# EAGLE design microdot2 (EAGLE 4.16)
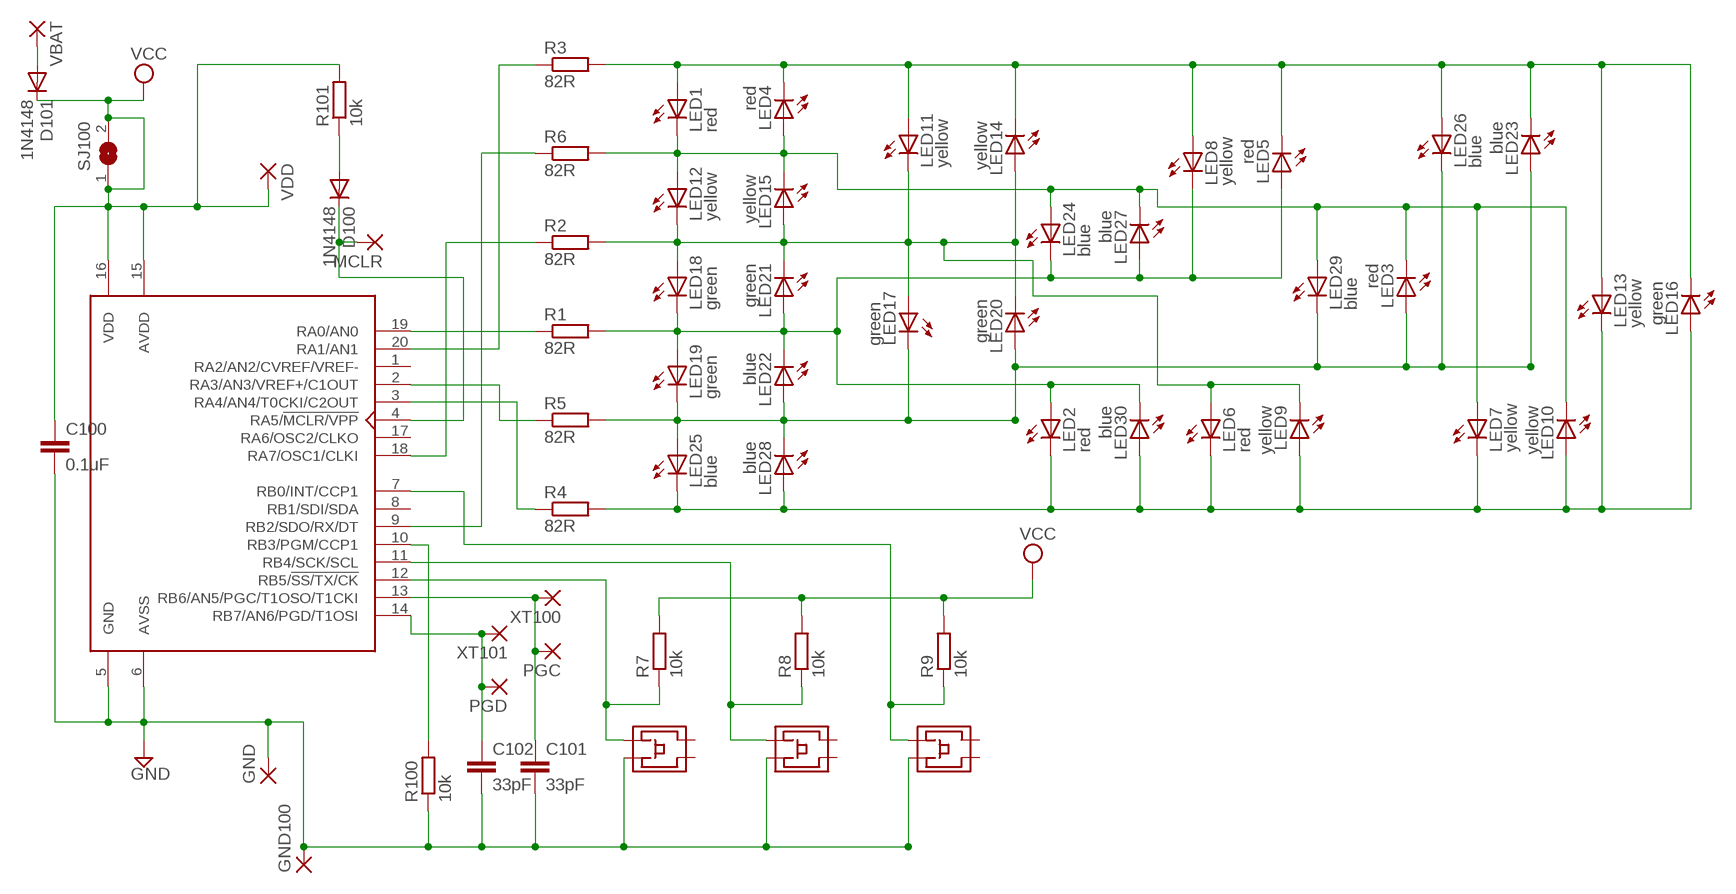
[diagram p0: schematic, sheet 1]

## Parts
C100  0.1uF  C-EUC0805K  [C0805K]
C101  33pF  C-EUC0805K  [C0805K]
C102  33pF  C-EUC0805K  [C0805K]
D100  1N4148  DIODE-MINIMELF  [MINIMELF]
D101  1N4148  DIODE-MINIMELF  [MINIMELF]
GND  SMD5  [SMD5]
GND100  SMD2  [SMD2]
LED1  red  LEDCHIPLED_1206  [CHIPLED_1206]
LED2  red  LEDCHIPLED_1206  [CHIPLED_1206]
LED3  red  LEDCHIPLED_1206  [CHIPLED_1206]
LED4  red  LEDCHIPLED_1206  [CHIPLED_1206]
LED5  red  LEDCHIPLED_1206  [CHIPLED_1206]
LED6  red  LEDCHIPLED_1206  [CHIPLED_1206]
LED7  yellow  LEDCHIPLED_1206  [CHIPLED_1206]
LED8  yellow  LEDCHIPLED_1206  [CHIPLED_1206]
LED9  yellow  LEDCHIPLED_1206  [CHIPLED_1206]
LED10  yellow  LEDCHIPLED_1206  [CHIPLED_1206]
LED11  yellow  LEDCHIPLED_1206  [CHIPLED_1206]
LED12  yellow  LEDCHIPLED_1206  [CHIPLED_1206]
LED13  yellow  LEDCHIPLED_1206  [CHIPLED_1206]
LED14  yellow  LEDCHIPLED_1206  [CHIPLED_1206]
LED15  yellow  LEDCHIPLED_1206  [CHIPLED_1206]
LED16  green  LEDCHIPLED_1206  [CHIPLED_1206]
LED17  green  LEDCHIPLED_1206  [CHIPLED_1206]
LED18  green  LEDCHIPLED_1206  [CHIPLED_1206]
LED19  green  LEDCHIPLED_1206  [CHIPLED_1206]
LED20  green  LEDCHIPLED_1206  [CHIPLED_1206]
LED21  green  LEDCHIPLED_1206  [CHIPLED_1206]
LED22  blue  LEDCHIPLED_1206  [CHIPLED_1206]
LED23  blue  LEDCHIPLED_1206  [CHIPLED_1206]
LED24  blue  LEDCHIPLED_1206  [CHIPLED_1206]
LED25  blue  LEDCHIPLED_1206  [CHIPLED_1206]
LED26  blue  LEDCHIPLED_1206  [CHIPLED_1206]
LED27  blue  LEDCHIPLED_1206  [CHIPLED_1206]
LED28  blue  LEDCHIPLED_1206  [CHIPLED_1206]
LED29  blue  LEDCHIPLED_1206  [CHIPLED_1206]
LED30  blue  LEDCHIPLED_1206  [CHIPLED_1206]
MCLR  SMD2  [SMD2]
PGC  SMD2  [SMD2]
PGD  SMD2  [SMD2]
R1  82R  R-EU_M0805  [M0805]
R2  82R  R-EU_M0805  [M0805]
R3  82R  R-EU_M0805  [M0805]
R4  82R  R-EU_M0805  [M0805]
R5  82R  R-EU_M0805  [M0805]
R6  82R  R-EU_M0805  [M0805]
R7  10k  R-EU_M0805  [M0805]
R8  10k  R-EU_M0805  [M0805]
R9  10k  R-EU_M0805  [M0805]
R100  10k  R-EU_M0805  [M0805]
R101  10k  R-EU_M0805  [M0805]
SJ100  SJ  [SJ]
U100  16F88SOIP20  [SSOP20]
U$1  SMDMICROSWITCH  [SMDMICROSWITCH]
U$2  SMDMICROSWITCH  [SMDMICROSWITCH]
U$3  SMDMICROSWITCH  [SMDMICROSWITCH]
VBAT  SMD5  [SMD5]
VDD  SMD2  [SMD2]
XT100  SMD2  [SMD2]
XT101  SMD2  [SMD2]

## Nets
GND: C100.2 C101.2 C102.2 GND100.1(P) GND.1(P) R100.1 U100.5(GND) U100.6(AVSS) U$1.L1 U$2.L1 U$3.L1
N$1: R1.1 U100.19(RA0/AN0)
N$2: R2.1 U100.18(RA7/OSC1/CLKI)
N$3: R4.1 U100.3(RA4/AN4/T0CKI/C2OUT)
N$4: D101.A VBAT.1(P)
N$7: R100.2 U100.10(RB3/PGM/CCP1)
N$8: R8.1 U100.11(RB4/SCK/SCL) U$3.L2
N$9: D100.A R101.1
N$10: D100.C MCLR.1(P) U100.4(RA5/!MCLR/VPP)
N$13: R7.1 U100.12(RB5/!SS/TX/CK) U$2.L2
N$17: R6.1 U100.9(RB2/SDO/RX/DT)
N$20: R3.1 U100.20(RA1/AN1)
N$21: R5.1 U100.2(RA3/AN3/VREF+/C1OUT)
N$23: R9.1 U100.7(RB0/INT/CCP1) U$1.L2
PGC: C101.1 PGC.1(P) U100.13(RB6/AN5/PGC/T1OSO/T1CKI) XT100.1(P)
PGD: C102.1 PGD.1(P) U100.14(RB7/AN6/PGD/T1OSI) XT101.1(P)
R1: LED1.A LED4.C LED5.C LED8.A LED11.A LED13.A LED14.C LED16.C LED23.C LED26.A R3.2
R2: LED1.C LED3.C LED4.A LED7.A LED10.C LED12.A LED15.C LED24.A LED27.C LED29.A R6.2
R3: LED6.A LED9.C LED11.C LED12.C LED14.A LED15.A LED17.A LED18.A LED20.C LED21.C R2.2
R4: LED2.A LED5.A LED8.C LED18.C LED19.A LED21.A LED22.C LED24.C LED27.A LED30.C R1.2
R5: LED3.A LED17.C LED19.C LED20.A LED22.A LED23.A LED25.A LED26.C LED28.C LED29.C R5.2
R6: LED2.C LED6.C LED7.C LED9.A LED10.A LED13.C LED16.A LED25.C LED28.A LED30.A R4.2
VCC: C100.1 D101.C R7.2 R8.2 R9.2 R101.2 SJ100.1 SJ100.2 U100.15(AVDD) U100.16(VDD) VDD.1(P)
Unconnected: U100.1(RA2/AN2/CVREF/VREF-) U100.8(RB1/SDI/SDA) U100.17(RA6/OSC2/CLKO) U$1.R1 U$1.R2 U$2.R1 U$2.R2 U$3.R1 U$3.R2

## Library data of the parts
C100-C102 = rcl:C-EU: CAPACITOR, European symbol
D100 D101 = diode:DIODE-: DIODE
GND VBAT = wirepad:SMD5: SMD PAD
GND100 MCLR PGC PGD VDD XT100 XT101 = wirepad:SMD2: SMD PAD
LED1-LED30 = led:LED: LED
R1-R9 R100 R101 = rcl:R-EU_: RESISTOR, European symbol
SJ100 = jumper:SJ: SMD solder JUMPER
U100 = microchip:16F88SOIP20
U$1-U$3 = custom:SMDMICROSWITCH

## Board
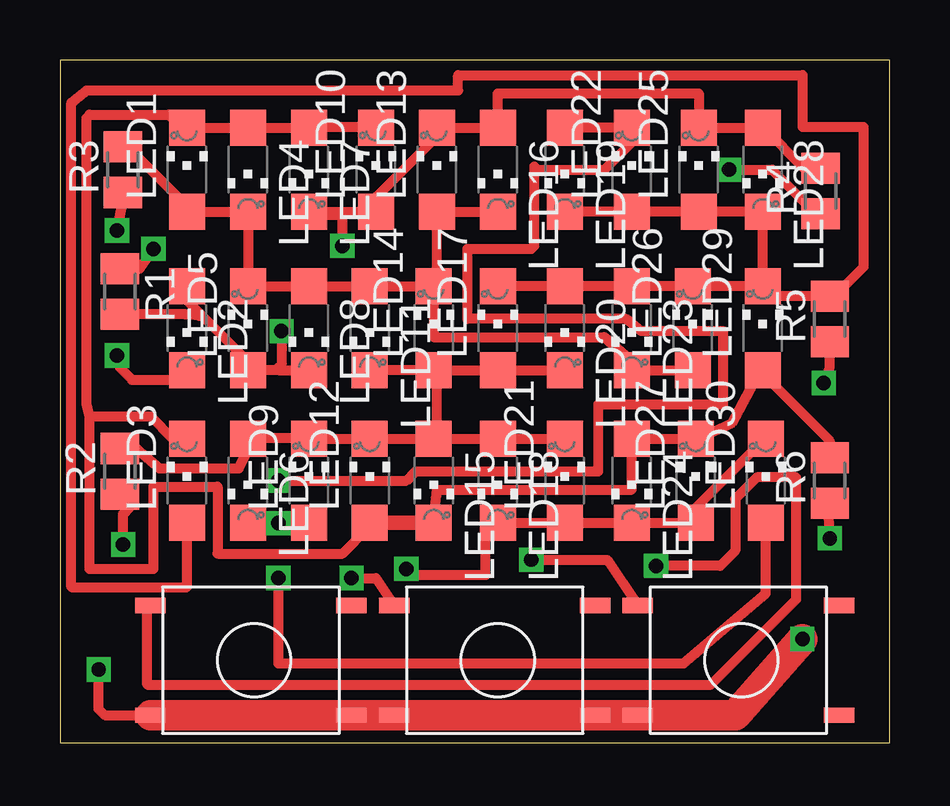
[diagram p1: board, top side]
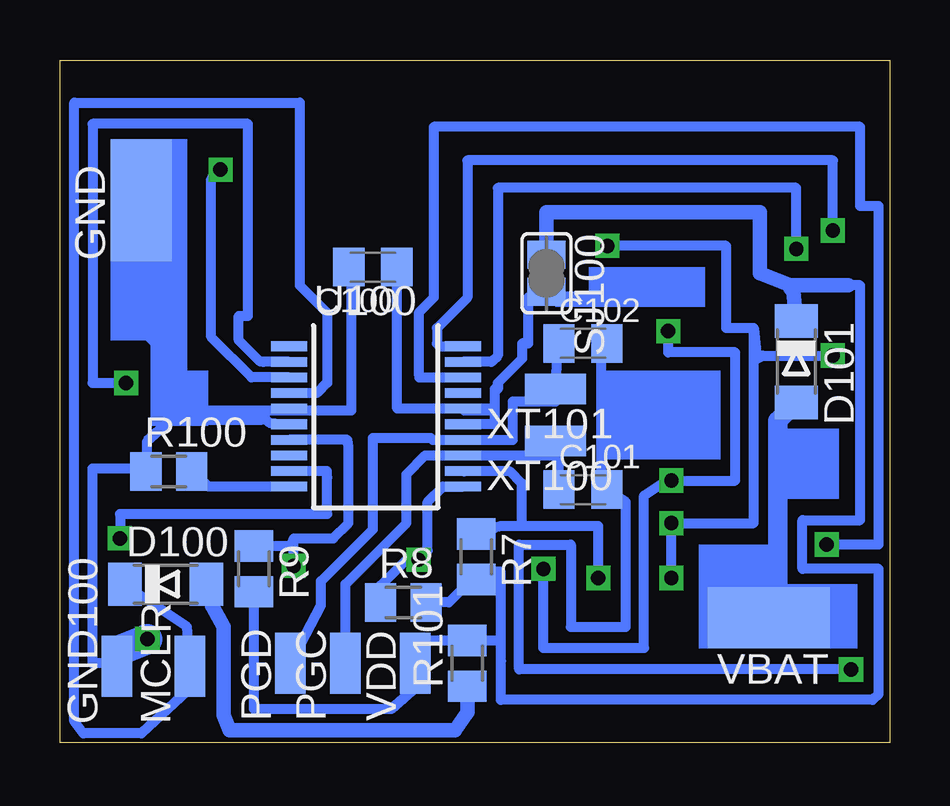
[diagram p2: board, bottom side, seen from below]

Size 34.59 x 28.44 mm. Coordinates in mm from the lower left corner, seen from the top.
Outline: 0,0 34.59,0 34.59,28.44 0,28.44 0,0
Copper layers (1*16): Top 0.035mm / dielectric 1.5mm / Bottom 0.035mm
Design rules "default": minimum track width 10mil, minimum drill 24mil, track to track 8mil, track to pad 8mil, pad to pad 8mil, via to via 8mil, smd to smd 8mil, copper to edge 40mil, drill to drill 8mil, minimum pad ring 10mil, minimum via ring 8mil, stop-mask expansion 4mil, vias tented up to drill 0mil, thermal gap 10mil

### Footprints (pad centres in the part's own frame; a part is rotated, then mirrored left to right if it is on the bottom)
C0805K = smd 1.3 x 1.6: 1 -1,0; 2 1,0
MINIMELF = smd 1.4 x 1.8: A 1.7,0; C -1.7,0
SMD5 = smd 2.54 x 5.08: 1 0,0
SMD2 = smd 1.27 x 2.54: 1 0,0
CHIPLED_1206 = smd 1.5 x 1.5: A 0,-1.75; C 0,1.75
M0805 = smd 1.3 x 1.6: 1 -0.95,0; 2 0.95,0
SJ = smd 1.168 x 1.6: 1 -0.762,0; 2 0.762,0
SSOP20 = smd 0.4 x 1.5: 1 -2.925,-3.625; 2 -2.275,-3.625; 3 -1.625,-3.625; 4 -0.975,-3.625; 5 -0.325,-3.625; 6 0.325,-3.625; 7 0.975,-3.625; 8 1.625,-3.625; 9 2.275,-3.625; 10 2.925,-3.625; 11 2.925,3.625; 12 2.275,3.625; 13 1.625,3.625; 14 0.975,3.625; 15 0.325,3.625; 16 -0.325,3.625; 17 -0.975,3.625; 18 -1.625,3.625; 19 -2.275,3.625; 20 -2.925,3.625
SMDMICROSWITCH = smd 1.27 x 0.635: L1 0,0; L2 0,4.572; R1 8.382,0; R2 8.382,4.572

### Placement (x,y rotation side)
C100  21.55,19.81 180 bottom
C101  12.79,10.54 0 bottom
C102  12.79,16.63 0 bottom
D100  30.19,6.6 0 bottom
D101  3.9,15.87 270 bottom
GND  31.2,22.6 0 bottom
GND100  32.22,3.17 0 bottom
LED1  5.3,23.87 0 top
LED2  5.3,17.27 180 top
LED3  5.3,10.92 0 top
LED4  7.84,23.87 180 top
LED5  7.84,17.27 0 top
LED6  7.84,10.92 180 top
LED7  10.38,23.87 180 top
LED8  10.38,17.27 180 top
LED9  10.38,10.92 0 top
LED10  13.17,23.87 0 top
LED11  12.92,17.27 180 top
LED12  12.92,10.92 0 top
LED13  15.71,23.87 0 top
LED14  15.58,17.27 0 top
LED15  15.58,10.92 180 top
LED16  18.25,23.87 180 top
LED17  18.25,17.27 0 top
LED18  18.25,10.92 180 top
LED19  21.04,23.87 180 top
LED20  21.04,17.27 180 top
LED21  21.04,10.92 0 top
LED22  23.84,23.87 0 top
LED23  23.84,17.27 180 top
LED24  23.84,10.92 180 top
LED25  26.63,23.87 0 top
LED26  26.38,17.27 0 top
LED27  26.5,10.92 0 top
LED28  29.3,23.87 180 top
LED29  29.3,17.27 0 top
LED30  29.43,10.92 0 top
MCLR  29.17,3.17 0 bottom
PGC  22.7,3.3 0 bottom
PGD  24.98,3.3 0 bottom
R1  2.5,18.79 270 top
R2  2.5,11.3 90 top
R3  2.63,23.87 90 top
R4  31.71,22.98 90 top
R5  32.09,17.65 90 top
R6  32.09,10.92 90 top
R7  17.23,7.74 270 bottom
R8  20.28,5.84 0 bottom
R9  26.5,7.23 270 bottom
R100  30.06,11.3 0 bottom
R101  17.62,3.3 90 bottom
SJ100  14.31,19.55 270 bottom
U100  21.43,13.58 270 bottom
U$1  3.77,1.14 0 top
U$2  13.93,1.14 0 top
U$3  24.09,1.14 0 top
VBAT  5.04,5.2 90 bottom
VDD  19.77,3.3 0 bottom
XT100  13.93,12.57 90 bottom
XT101  13.93,14.73 90 bottom

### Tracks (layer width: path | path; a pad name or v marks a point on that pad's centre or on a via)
GND  (via drill 0.6)
  Top 0.406: U$2.L1 1.87,1.14 1.61,1.39 v1.61,3.04
  Top 1.27: U$1.L1 U$2.L1 U$3.L1 28.16,1.14 v30.95,4.31
  Bottom 0.406: C102.2 12.03,16.63 12.03,10.03 11.01,10.03 | U100.6 25.87,13.33 26.18,13.64 26.25,13.64 26.5,13.84 24.85,13.84 | 24.85,13.84 25.11,13.91 U100.5 | C100.2 22.44,19.81 22.44,13.84 24.85,13.84 | 32.22,3.04 32.22,3.3 33.24,3.3 33.24,11.42 31.08,11.42 31.01,11.36 R100.1 31.08,11.3 30.95,11.42 30.95,12.57 29.75,13.64 | 31.2,17.52 GND.1 | v1.61,3.04 15.46,3.04 15.46,8.25 13.3,8.25 13.3,4.82 11.01,4.82 11.01,10.03 | 11.01,10.03 C101.2
  Bottom 0.813: 26.25,13.64 29.75,13.64 29.75,16.07 31.2,17.52
  Bottom 1.27: GND100.1 32.22,3.04 32.22,3.81 v30.95,4.31
N$1  (via drill 0.6)
  Top 0.406: R1.1 3.32,19.74 v3.9,20.57
  Bottom 0.406: U100.19 16.61,15.86 16.34,16.12 16.34,23.11 3.9,23.11 v3.9,20.57
N$2  (via drill 0.6)
  Top 0.406: R2.1 2.44,10.35 2.38,10.28 2.88,9.77 2.63,9.52 v2.63,8.25
  Bottom 0.406: U100.18 19.62,15.21 19.65,15.36 19.65,17.9 19.01,18.54 19.01,25.65 1.23,25.65 1.23,22.35 0.47,22.35 0.47,8.25 v2.63,8.25
N$3  (via drill 0.6)
  Top 0.406: v27.9,23.87 29.68,23.87 31.08,22.47 31.2,22.47 31.71,21.97 R4.1
  Bottom 0.406: U100.3 26.61,15.21 28.28,16.89 28.28,23.49 v27.9,23.87
N$4
  Bottom 0.813: VBAT.1 4.66,5.2 4.66,13.41 D101.A
N$7
  Bottom 0.406: R100.2 29.05,11.3 28.41,10.66 U100.10
N$8  (via drill 0.6)
  Top 0.406: 24.22,5.58 U$3.L2 22.82,7.62 v19.65,7.62
  Bottom 0.406: U100.11 18.64,10.66 19.27,10.03 19.27,8 v19.65,7.62 20.16,7.62 21.23,6.54 R8.1
N$9
  Bottom 0.61: D100.A 28.23,5.66 27.78,4.82 27.78,1.14 27.52,0.5 18.12,0.5 17.62,1.26 R101.1
N$10
  Bottom 0.406: D100.C 31.63,6.39 29.3,4.82 MCLR.1 29.3,2.15 31.2,0.38 33.62,0.38 34,0.88 34,26.66 24.6,26.66 24.6,19.05 23.46,17.9 23.46,14.98 23.88,14.56 U100.4
N$13  (via drill 0.6)
  Top 0.406: U$2.L2 13.17,6.85 v12.15,6.85
  Bottom 0.406: v12.15,6.85 12.15,9.01 15.2,9.01 | 15.2,9.01 15.33,9.01 15.33,10.79 15.84,11.3 17.74,11.3 17.75,11.31 U100.12 | R7.1 16.47,8.95 16.22,9.01 15.2,9.01
N$17  (via drill 0.6)
  Top 0.406: 32.03,9.97 31.97,10.03 | 32.03,9.97 R6.1 | v32.09,8.5 32.03,9.97
  Bottom 0.406: U100.9 23.47,11.31 23.46,11.04 23.46,9.52 32.09,9.52 v32.09,8.5
N$20  (via drill 0.6)
  Top 0.406: 2.56,22.54 2.5,22.6 | 2.56,22.54 R3.1 | v2.38,21.33 2.63,22.6 2.56,22.54
  Bottom 0.406: U100.20 18.76,16.51 18.89,16.63 18.89,17.27 17.62,18.54 17.62,24.25 2.38,24.25 v2.38,21.33
N$21  (via drill 0.6)
  Top 0.406: R5.1 32.09,15.62 v31.84,14.98
  Bottom 0.406: v31.84,14.98 33.24,14.98 33.24,25.78 26.76,25.78 26.76,17.78 27.14,17.78 27.14,16.76 26.25,15.87 26.12,15.87 26.11,15.86 U100.2
N$23  (via drill 0.6)
  Top 0.406: v24.85,7.36 27.52,7.36 28.16,8 28.16,10.15 29.05,11.04 30.7,11.04 30.7,5.96 27.14,2.41 3.65,2.41 3.65,5.71 U$1.L2
  Bottom 0.406: U100.7 22.61,12.61 22.57,12.31 22.57,9.14 23.2,8.5 24.85,8.5 24.85,8.38 | v24.85,7.36 24.85,8.38 | R9.1 25.05,8.18 24.85,8.38
PGC
  Bottom 0.406: 13.8,12.19 13.8,11.96 U100.13 19.37,11.96 20.16,11.17 20.16,9.14 22.7,6.6 PGC.1 23.08,2.92 | 13.8,12.19 XT100.1 | C101.1 13.8,10.03 13.8,12.19
PGD
  Bottom 0.406: C102.1 13.8,16.63 XT101.1 13.93,14.22 15.71,14.22 15.71,12.61 U100.14 19.05,12.61 19.14,12.7 21.55,12.7 21.55,8.88 23.71,6.73 23.71,5.71 PGD.1
R1
  Top 0.406: 23.74,15.52 LED23.C | 23.74,15.52 LED26.A | 23.74,15.52 23.71,15.49 | 15.71,22.09 LED13.A | LED16.C 15.74,22.12 15.71,22.09 | 15.71,22.09 15.71,19.17 15.58,19.05 | LED11.A 12.89,19.02 12.79,18.92 | LED11.A LED14.C 15.61,19.02 15.58,19.05 | LED8.A 10.35,19.02 10.25,18.92 | LED8.A LED11.A | LED8.A 8.06,19.02 7.96,18.92 7.86,19.02 LED5.C 7.84,22.09 7.81,22.12 | 7.81,22.12 7.71,22.22 | 7.81,22.12 LED4.C 5.2,22.12 5.17,22.09 LED1.A 5.17,22.47 3.26,24.38 2.63,24.38 R3.2 | 23.74,15.52 23.74,15.97 22.7,16.89 15.58,16.89 15.58,19.05
R2
  Top 0.406: 10.48,25.62 LED7.A | 10.48,25.62 LED4.A 7.84,25.65 7.81,25.62 LED1.C 5.17,25.52 4.53,26.16 1.23,26.16 1.1,26.03 1.1,14.09 1.23,13.58 | 10.48,25.62 10.5,25.65 13.04,25.65 13.07,25.62 LED10.C | LED24.A 23.74,12.67 23.71,12.7 | LED24.A LED27.C 26.6,12.67 28.03,13.33 28.79,14.73 28.79,15.49 LED29.A 29.2,15.52 29.17,15.49 32.09,12.57 R6.2 | LED15.C 15.71,10.54 23.84,10.54 LED24.A | LED24.A 23.84,12.7 | LED3.C 4.69,12.67 3.77,13.58 1.23,13.58 | LED12.A 12.89,9.17 12.89,8.98 11.77,7.87 6.57,7.87 6.57,10.66 3.9,10.66 3.9,7.23 1.23,7.23 1.23,13.58
  Top 0.61: LED12.A 12.94,9.17 13.04,9.27 13.14,9.17 LED15.C
R3
  Top 0.406: LED17.A 18.22,15.52 18.12,15.62 | LED17.A LED20.C | 15.71,15.49 LED14.A 12.94,15.52 12.92,15.49 LED11.C | LED17.A 15.74,15.52 15.71,15.49 | LED21.C 18.28,12.67 18.25,12.7 LED18.A 15.74,12.67 15.71,12.7 LED15.A | LED12.C 12.82,12.67 12.79,12.7 | LED12.C LED15.A | 10.28,12.67 LED9.C | 10.28,12.67 LED12.C | 10.28,12.67 10.25,12.7 7.84,12.7 LED6.A 7.84,12.57 7.96,12.44 7.46,11.42 4.15,11.42 3.2,12.25 R2.2 | LED15.A 15.61,12.67 15.58,12.7 15.71,12.82 15.71,15.49
R4  (via drill 0.6)
  Top 0.406: LED24.C 23.81,9.17 23.71,9.27 | LED24.C LED27.A 26.5,9.77 29.43,12.7 LED30.C | LED24.C 21.2,9.17 21.17,9.14 21.14,9.17 LED21.A 18.41,9.17 18.38,9.14 18.35,9.17 LED18.C 18.25,9.01 17.74,8.5 17.74,6.98 14.95,6.98 v14.44,7.23 | LED19.A 21.07,25.62 21.17,25.52 21.27,25.62 LED22.C 23.84,25.01 22.7,23.87 19.9,23.87 19.77,24 19.77,20.7 19.65,20.57 16.98,20.57 16.98,17.65 23.58,17.65 24.22,17.14 27.65,17.14 27.65,14.09 22.44,14.09 22.44,11.3 14.82,11.3 14.44,10.92 v9.11,10.92 | 7.74,15.52 LED5.A | 9.11,15.52 7.74,15.52 | 9.11,15.52 LED8.C | 7.74,15.52 7.71,15.49 | 9.11,15.52 9.11,15.62 9.23,15.74 v9.23,17.14 | 7.74,15.52 7.74,15.97 5.87,17.84 | 5.87,17.84 5.3,18.41 5.3,18.79 5.17,18.92 5.27,19.02 LED2.A | 5.87,17.84 5.8,17.78 5.23,17.84 R1.2
  Bottom 0.406: v14.44,7.23 14.44,3.93 10.25,3.93 10.25,10.28 9.11,11.04 v9.11,10.92 6.44,10.92 6.44,16.25 9.23,16.25 v9.23,17.14
R5
  Top 0.406: LED26.C 26.28,19.02 26.25,19.05 | LED29.C LED26.C | LED26.C 23.94,19.02 23.84,18.92 LED23.A LED20.A | LED20.A 20.95,19.02 20.92,19.05 | 18.15,19.02 LED17.C | LED20.A 18.15,19.02 | 18.15,19.02 18.12,19.05 | LED19.C 23.81,22.12 23.84,22.09 LED22.A 26.48,22.12 26.5,22.09 26.53,22.12 LED25.A 29.27,22.12 29.3,22.09 LED28.C LED29.C | LED29.C 29.3,18.92 | LED29.C 29.4,19.02 29.43,19.05 29.87,18.6 R5.2 32.09,18.41 33.49,19.81 33.49,25.65 30.95,25.65 30.95,27.81 16.6,27.81 16.6,27.17 1.1,27.17 0.47,26.66 0.47,6.47 5.3,6.47 LED3.A
R6  (via drill 0.6)
  Top 0.406: LED16.A 18.5,25.52 18.41,25.62 LED16.A | LED16.A LED13.C 15.71,25.52 15.84,25.4 13.17,22.73 LED10.A 10.53,22.12 10.38,21.97 | 10.38,21.97 LED7.C | LED25.C 26.41,25.62 26.38,25.65 | LED25.C LED28.A 29.3,25.65 31.02,23.93 R4.2 | LED16.A 18.25,27.05 26.63,27.05 LED25.C | 8.22,9.27 7.71,9.27 7.81,9.17 LED6.C 7.84,9.14 v9.11,9.14 10.25,9.14 10.28,9.17 LED9.A | LED2.C 5.3,15.49 4.92,15.11 3.01,15.11 2.5,15.62 v2.38,16.12 | 10.38,21.97 11.77,21.97 v11.77,20.7 | LED30.A 29.43,6.22 26,3.3 9.11,3.3 v9.11,6.85
  Bottom 0.406: 5.68,17.27 6.82,17.27 6.82,20.7 v11.77,20.7 | 5.68,17.27 5.55,16 5.3,16.12 v2.38,16.12 | v9.11,6.85 v9.11,9.14 5.68,9.14 5.68,17.27
VCC
  Bottom 0.406: U100.15 16.47,13.26 16.47,13.84 17.74,13.84 17.74,13.91 | 17.74,13.91 16.47,13.91 16.47,14.73 16.34,14.73 16.34,14.98 15.33,16 15.33,16.63 15.07,16.63 15.07,18.54 SJ100.2 SJ100.1 | 17.74,13.91 U100.16 20.54,13.91 20.54,19.81 C100.1 | 1.74,19.05 1.23,19.05 1.23,9.27 3.65,9.27 3.65,7.23 0.47,7.23 0.47,2.03 0.72,1.77 16.22,1.77 16.22,3.42 | 16.22,3.42 16.22,3.36 | 16.22,3.42 16.22,4.19 | 16.22,4.19 16.22,7.11 17.23,7.11 R7.2 17.23,6.98 18.38,5.84 R8.2 | 16.22,4.19 16.28,4.25 R101.2 19.71,4.25 19.77,4.19 VDD.1 19.77,2.28 20.79,1.39 26.5,1.39 R9.2
  Bottom 0.61: SJ100.1 14.31,22.09 5.42,22.09 5.42,19.55 4.15,19.05 | 1.74,19.05 4.15,19.05 | 4.15,19.05 4.15,18.92 4.03,18.79 D101.C
(copper drawn outside any net)
  shapes: Bottom area x9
